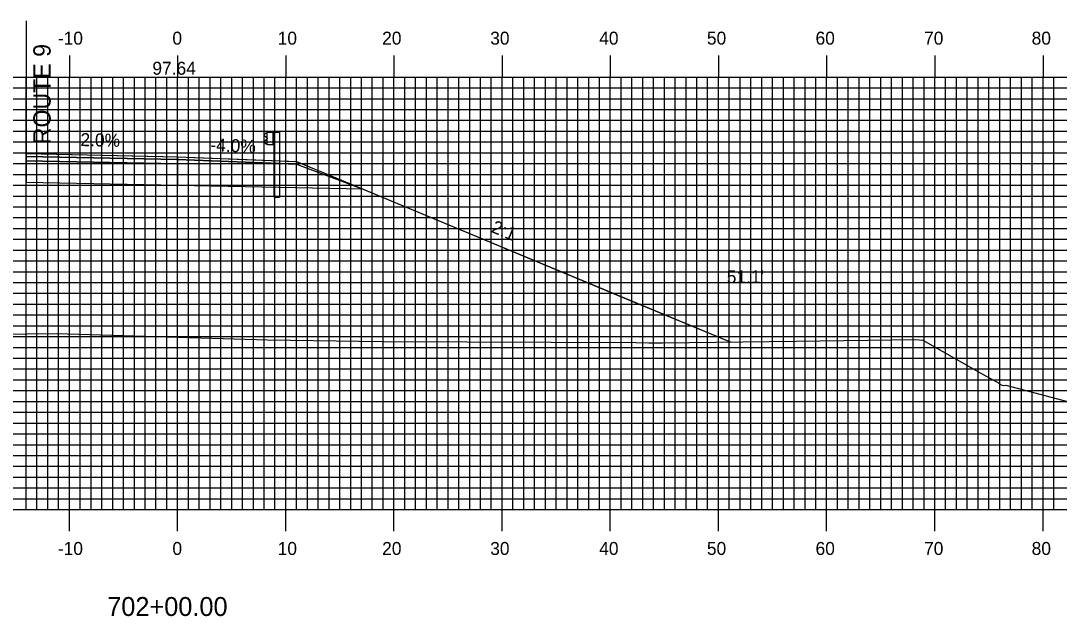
# Model space of a CAD drawing. Extents: x 852936 to 853279, y 364366 to 364586.
# Drawn here: x 853087.2 to 853183.2, y 364428.9 to 364484 of the extents above; entities that cross this region are included whole.
import ezdxf

# ---------------------------------------------------------------- set-up
doc = ezdxf.new("R2010")
doc.units = 0
for name, color, linetype in [('ANNOTATION', 7, 'Continuous'), ('D_Guardrail_Beam_Rt', 7, 'Continuous'), ('D_Roadway_Centerline', 7, 'Continuous'), ('D_Roadway_Centerline_Text', 7, 'Continuous'), ('D_Roadway_Edge_Shoulder', 7, 'Continuous'), ('D_Roadway_Edge_TW', 7, 'Continuous'), ('D_Roadway_Pavement', 7, 'Continuous'), ('D_Roadway_SlopeLines', 7, 'Continuous'), ('D_Roadway_SubGrade', 7, 'Continuous'), ('D_Text_Standard', 7, 'Continuous'), ('H_V ANNOTATION', 7, 'Continuous'), ('MAJOR', 7, 'Continuous'), ('MINOR', 7, 'Continuous'), ('S_Roadway_Centerline', 7, 'Continuous')]:
    doc.layers.add(name, color=color, linetype=linetype)

msp = doc.modelspace()

# ---------------------------------------------------------------- linework, layer by layer
at = {"layer": 'D_Guardrail_Beam_Rt'}
for p, q in [((853109.962, 364473.605), (853109.888, 364473.59)), ((853109.962, 364473.688), (853110.65, 364473.688)), ((853109.962, 364472.522), (853109.962, 364473.688)), ((853110.483, 364473.688), (853110.483, 364472.522)), ((853110.587, 364473.688), (853110.587, 364472.522)), ((853110.65, 364473.688), (853111.121, 364473.688)), ((853110.65, 364473.688), (853110.65, 364472.522)), ((853111.121, 364473.688), (853111.121, 364467.688)), ((853109.872, 364473.584), (853109.729, 364473.484)), ((853109.729, 364473.341), (853109.924, 364473.205)), ((853109.924, 364473.006), (853109.729, 364472.869)), ((853109.729, 364472.726), (853109.872, 364472.626)), ((853109.958, 364473.14), (853109.958, 364473.07)), ((853109.888, 364472.62), (853109.962, 364472.605)), ((853110.65, 364472.522), (853109.962, 364472.522)), ((853110.629, 364467.688), (853110.629, 364472.522)), ((853110.629, 364467.688), (853111.121, 364467.688))]:
    msp.add_line(p, q, dxfattribs=at)
for centre, major_axis, start_param, end_param in [((853109.779, 364473.412), (-0.0877, 0), 5.323254, 7.243116), ((853109.779, 364472.798), (-0.0877, 0), 5.323254, 7.243116), ((853109.896, 364473.55), (-0.0417, 0), 4.907132, 5.323254), ((853109.879, 364473.14), (0.0789, 0), 0, 0.959931), ((853109.879, 364473.07), (0.0789, 0), 5.323254, 6.283185), ((853109.896, 364472.66), (-0.0417, 0), 0.959931, 1.376053)]:
    msp.add_ellipse(centre, major_axis=major_axis, ratio=0.995501, start_param=start_param, end_param=end_param, dxfattribs=at)
at = {"layer": 'D_Roadway_Centerline'}
msp.add_lwpolyline([(853087.691, 364471.705), (853097.591, 364471.507), (853101.691, 364471.425), (853107.349, 364471.199), (853109.691, 364471.105), (853111.813, 364471.02), (853112.691, 364470.985), (853117.044, 364469.168), (853118.859, 364468.415), (853142.791, 364458.424), (853152.76, 364454.288)], dxfattribs=at)
at = {"layer": 'D_Roadway_Edge_Shoulder'}
for points in [[(853101.691, 364471.425), (853112.691, 364470.985), (853112.691, 364470.735), (853101.691, 364471.175)], [(853101.691, 364471.425), (853109.691, 364471.105), (853109.691, 364471.105), (853112.691, 364470.985), (853112.691, 364470.735), (853101.691, 364471.175)], [(853101.691, 364471.425), (853109.691, 364471.105), (853109.691, 364471.105), (853112.691, 364470.985), (853112.691, 364470.735), (853101.691, 364471.175)], [(853101.691, 364471.425), (853112.691, 364470.985), (853112.691, 364470.735), (853101.691, 364471.175)], [(853101.691, 364471.425), (853112.691, 364470.985), (853112.691, 364470.735), (853101.691, 364471.175)]]:
    msp.add_lwpolyline(points, close=True, dxfattribs=at)
at = {"layer": 'D_Roadway_Edge_TW'}
msp.add_lwpolyline([(853087.691, 364471.705), (853101.691, 364471.425), (853101.691, 364471.175), (853087.691, 364471.455)], close=True, dxfattribs=at)
msp.add_lwpolyline([(853087.691, 364471.705), (853101.691, 364471.425), (853101.691, 364471.175), (853087.691, 364471.455)], close=True, dxfattribs=at)
msp.add_lwpolyline([(853087.691, 364471.705), (853101.691, 364471.425), (853101.691, 364471.175), (853087.691, 364471.455)], close=True, dxfattribs=at)
msp.add_lwpolyline([(853087.691, 364471.705), (853101.691, 364471.425), (853101.691, 364471.175), (853087.691, 364471.455)], close=True, dxfattribs=at)
at = {"layer": 'D_Roadway_Pavement'}
msp.add_lwpolyline([(853087.691, 364471.455), (853101.691, 364471.175), (853101.691, 364470.758), (853087.691, 364471.038)], close=True, dxfattribs=at)
msp.add_lwpolyline([(853087.691, 364471.455), (853101.691, 364471.175), (853101.691, 364470.758), (853087.691, 364471.038)], close=True, dxfattribs=at)
msp.add_lwpolyline([(853087.691, 364471.455), (853101.691, 364471.175), (853101.691, 364470.758), (853087.691, 364471.038)], close=True, dxfattribs=at)
msp.add_lwpolyline([(853087.691, 364471.455), (853101.691, 364471.175), (853101.691, 364470.758), (853087.691, 364471.038)], close=True, dxfattribs=at)
msp.add_lwpolyline([(853101.691, 364471.175), (853101.691, 364470.758)], dxfattribs=at)
msp.add_lwpolyline([(853101.691, 364471.175), (853101.691, 364470.758)], dxfattribs=at)
msp.add_lwpolyline([(853101.691, 364471.175), (853101.691, 364470.758)], dxfattribs=at)
msp.add_lwpolyline([(853101.691, 364471.175), (853101.691, 364470.758)], dxfattribs=at)
msp.add_lwpolyline([(853101.691, 364471.175), (853101.691, 364470.758)], dxfattribs=at)
msp.add_lwpolyline([(853101.691, 364471.175), (853101.691, 364470.758)], dxfattribs=at)
msp.add_lwpolyline([(853101.691, 364471.175), (853101.691, 364470.758)], dxfattribs=at)
msp.add_lwpolyline([(853101.691, 364471.175), (853101.691, 364470.758)], dxfattribs=at)
msp.add_lwpolyline([(853101.691, 364471.175), (853101.691, 364470.758)], dxfattribs=at)
msp.add_lwpolyline([(853101.691, 364471.175), (853101.691, 364470.758)], dxfattribs=at)
msp.add_lwpolyline([(853101.691, 364471.175), (853101.691, 364470.758)], dxfattribs=at)
msp.add_lwpolyline([(853101.691, 364471.175), (853101.691, 364470.758)], dxfattribs=at)
msp.add_lwpolyline([(853101.691, 364471.175), (853101.691, 364470.758)], dxfattribs=at)
msp.add_lwpolyline([(853101.691, 364471.175), (853101.691, 364470.758)], dxfattribs=at)
at = {"layer": 'D_Roadway_SlopeLines'}
msp.add_lwpolyline([(853112.691, 364470.985), (853152.76, 364454.288)], dxfattribs=at)
msp.add_lwpolyline([(853112.691, 364470.985), (853152.76, 364454.288)], dxfattribs=at)
msp.add_lwpolyline([(853112.691, 364470.985), (853152.76, 364454.288)], dxfattribs=at)
msp.add_lwpolyline([(853112.691, 364470.985), (853152.76, 364454.288)], dxfattribs=at)
at = {"layer": 'D_Roadway_SubGrade'}
msp.add_line((853087.691, 364483.995), (853087.691, 364469.038), dxfattribs=at)
for points in [[(853087.691, 364471.038), (853101.691, 364470.758), (853101.691, 364468.758), (853087.691, 364469.038)], [(853087.691, 364471.038), (853101.691, 364470.758), (853101.691, 364468.758), (853087.691, 364469.038)], [(853087.691, 364471.038), (853101.691, 364470.758), (853101.691, 364468.758), (853087.691, 364469.038)], [(853087.691, 364471.038), (853101.691, 364470.758), (853101.691, 364468.758), (853087.691, 364469.038)], [(853101.691, 364470.758), (853101.691, 364471.175), (853112.691, 364470.735), (853112.691, 364470.985), (853118.859, 364468.415), (853101.691, 364468.758)], [(853101.691, 364470.758), (853101.691, 364471.175), (853112.691, 364470.735), (853112.691, 364470.985), (853118.859, 364468.415), (853101.691, 364468.758)], [(853101.691, 364470.758), (853101.691, 364471.175), (853112.691, 364470.735), (853112.691, 364470.985), (853118.859, 364468.415), (853101.691, 364468.758)], [(853101.691, 364470.758), (853101.691, 364471.175), (853112.691, 364470.735), (853118.859, 364468.415), (853101.691, 364468.758)], [(853101.691, 364470.758), (853101.691, 364471.175), (853112.691, 364470.735), (853112.691, 364470.985), (853118.859, 364468.415), (853101.691, 364468.758)]]:
    msp.add_lwpolyline(points, close=True, dxfattribs=at)
at = {"layer": 'MAJOR'}
for p, q in [((853091.691, 364480.791), (853091.691, 364478.787)), ((853101.691, 364480.791), (853101.691, 364478.787)), ((853111.691, 364480.791), (853111.691, 364478.787)), ((853121.691, 364480.791), (853121.691, 364478.787)), ((853131.691, 364480.791), (853131.691, 364478.787)), ((853141.691, 364480.791), (853141.691, 364478.787)), ((853151.691, 364480.791), (853151.691, 364478.787)), ((853161.691, 364480.791), (853161.691, 364478.787)), ((853171.691, 364480.791), (853171.691, 364478.787)), ((853181.691, 364480.791), (853181.691, 364478.787)), ((852961.691, 364478.787), (853241.691, 364478.787)), ((852961.691, 364478.787), (853241.691, 364478.787)), ((853091.691, 364438.787), (853091.691, 364478.787)), ((853101.691, 364438.787), (853101.691, 364478.787)), ((853111.691, 364438.787), (853111.691, 364478.787)), ((853121.691, 364438.787), (853121.691, 364478.787)), ((853131.691, 364438.787), (853131.691, 364478.787)), ((853141.691, 364438.787), (853141.691, 364478.787)), ((853151.691, 364438.787), (853151.691, 364478.787)), ((853161.691, 364438.787), (853161.691, 364478.787)), ((853171.691, 364438.787), (853171.691, 364478.787)), ((853181.691, 364438.787), (853181.691, 364478.787)), ((852961.691, 364473.787), (853241.691, 364473.787)), ((852961.691, 364468.787), (853241.691, 364468.787)), ((852961.691, 364463.787), (853241.691, 364463.787)), ((852961.691, 364458.787), (853241.691, 364458.787)), ((852961.691, 364453.787), (853241.691, 364453.787)), ((852961.691, 364448.787), (853241.691, 364448.787)), ((852961.691, 364443.787), (853241.691, 364443.787)), ((852961.691, 364438.787), (853241.691, 364438.787)), ((852961.691, 364438.787), (853241.691, 364438.787)), ((853091.691, 364436.783), (853091.691, 364438.787)), ((853101.691, 364436.783), (853101.691, 364438.787)), ((853111.691, 364436.783), (853111.691, 364438.787)), ((853121.691, 364436.783), (853121.691, 364438.787)), ((853131.691, 364436.783), (853131.691, 364438.787)), ((853141.691, 364436.783), (853141.691, 364438.787)), ((853151.691, 364436.783), (853151.691, 364438.787)), ((853161.691, 364436.783), (853161.691, 364438.787)), ((853171.691, 364436.783), (853171.691, 364438.787)), ((853181.691, 364436.783), (853181.691, 364438.787))]:
    msp.add_line(p, q, dxfattribs=at)
at = {"layer": 'MINOR'}
for p, q in [((853087.691, 364438.787), (853087.691, 364478.787)), ((853088.691, 364438.787), (853088.691, 364478.787)), ((853089.691, 364438.787), (853089.691, 364478.787)), ((853090.691, 364438.787), (853090.691, 364478.787)), ((853092.691, 364438.787), (853092.691, 364478.787)), ((853093.691, 364438.787), (853093.691, 364478.787)), ((853094.691, 364438.787), (853094.691, 364478.787)), ((853095.691, 364438.787), (853095.691, 364478.787)), ((853096.691, 364438.787), (853096.691, 364478.787)), ((853097.691, 364438.787), (853097.691, 364478.787)), ((853098.691, 364438.787), (853098.691, 364478.787)), ((853099.691, 364438.787), (853099.691, 364478.787)), ((853100.691, 364438.787), (853100.691, 364478.787)), ((853102.691, 364438.787), (853102.691, 364478.787)), ((853103.691, 364438.787), (853103.691, 364478.787)), ((853104.691, 364438.787), (853104.691, 364478.787)), ((853105.691, 364438.787), (853105.691, 364478.787)), ((853106.691, 364438.787), (853106.691, 364478.787)), ((853107.691, 364438.787), (853107.691, 364478.787)), ((853108.691, 364438.787), (853108.691, 364478.787)), ((853109.691, 364438.787), (853109.691, 364478.787)), ((853110.691, 364438.787), (853110.691, 364478.787)), ((853112.691, 364438.787), (853112.691, 364478.787)), ((853113.691, 364438.787), (853113.691, 364478.787)), ((853114.691, 364438.787), (853114.691, 364478.787)), ((853115.691, 364438.787), (853115.691, 364478.787)), ((853116.691, 364438.787), (853116.691, 364478.787)), ((853117.691, 364438.787), (853117.691, 364478.787)), ((853118.691, 364438.787), (853118.691, 364478.787)), ((853119.691, 364438.787), (853119.691, 364478.787)), ((853120.691, 364438.787), (853120.691, 364478.787)), ((853122.691, 364438.787), (853122.691, 364478.787)), ((853123.691, 364438.787), (853123.691, 364478.787)), ((853124.691, 364438.787), (853124.691, 364478.787)), ((853125.691, 364438.787), (853125.691, 364478.787)), ((853126.691, 364438.787), (853126.691, 364478.787)), ((853127.691, 364438.787), (853127.691, 364478.787)), ((853128.691, 364438.787), (853128.691, 364478.787)), ((853129.691, 364438.787), (853129.691, 364478.787)), ((853130.691, 364438.787), (853130.691, 364478.787)), ((853132.691, 364438.787), (853132.691, 364478.787)), ((853133.691, 364438.787), (853133.691, 364478.787)), ((853134.691, 364438.787), (853134.691, 364478.787)), ((853135.691, 364438.787), (853135.691, 364478.787)), ((853136.691, 364438.787), (853136.691, 364478.787)), ((853137.691, 364438.787), (853137.691, 364478.787)), ((853138.691, 364438.787), (853138.691, 364478.787)), ((853139.691, 364438.787), (853139.691, 364478.787)), ((853140.691, 364438.787), (853140.691, 364478.787)), ((853142.691, 364438.787), (853142.691, 364478.787)), ((853143.691, 364438.787), (853143.691, 364478.787)), ((853144.691, 364438.787), (853144.691, 364478.787)), ((853145.691, 364438.787), (853145.691, 364478.787)), ((853146.691, 364438.787), (853146.691, 364478.787)), ((853147.691, 364438.787), (853147.691, 364478.787)), ((853148.691, 364438.787), (853148.691, 364478.787)), ((853149.691, 364438.787), (853149.691, 364478.787)), ((853150.691, 364438.787), (853150.691, 364478.787)), ((853152.691, 364438.787), (853152.691, 364478.787)), ((853153.691, 364438.787), (853153.691, 364478.787)), ((853154.691, 364438.787), (853154.691, 364478.787)), ((853155.691, 364438.787), (853155.691, 364478.787)), ((853156.691, 364438.787), (853156.691, 364478.787)), ((853157.691, 364438.787), (853157.691, 364478.787)), ((853158.691, 364438.787), (853158.691, 364478.787)), ((853159.691, 364438.787), (853159.691, 364478.787)), ((853160.691, 364438.787), (853160.691, 364478.787)), ((853162.691, 364438.787), (853162.691, 364478.787)), ((853163.691, 364438.787), (853163.691, 364478.787)), ((853164.691, 364438.787), (853164.691, 364478.787)), ((853165.691, 364438.787), (853165.691, 364478.787)), ((853166.691, 364438.787), (853166.691, 364478.787)), ((853167.691, 364438.787), (853167.691, 364478.787)), ((853168.691, 364438.787), (853168.691, 364478.787)), ((853169.691, 364438.787), (853169.691, 364478.787)), ((853170.691, 364438.787), (853170.691, 364478.787)), ((853172.691, 364438.787), (853172.691, 364478.787)), ((853173.691, 364438.787), (853173.691, 364478.787)), ((853174.691, 364438.787), (853174.691, 364478.787)), ((853175.691, 364438.787), (853175.691, 364478.787)), ((853176.691, 364438.787), (853176.691, 364478.787)), ((853177.691, 364438.787), (853177.691, 364478.787)), ((853178.691, 364438.787), (853178.691, 364478.787)), ((853179.691, 364438.787), (853179.691, 364478.787)), ((853180.691, 364438.787), (853180.691, 364478.787)), ((853182.691, 364438.787), (853182.691, 364478.787)), ((852961.691, 364477.787), (853241.691, 364477.787)), ((852961.691, 364476.787), (853241.691, 364476.787)), ((852961.691, 364475.787), (853241.691, 364475.787)), ((852961.691, 364474.787), (853241.691, 364474.787)), ((852961.691, 364472.787), (853241.691, 364472.787)), ((852961.691, 364471.787), (853241.691, 364471.787)), ((852961.691, 364470.787), (853241.691, 364470.787)), ((852961.691, 364469.787), (853241.691, 364469.787)), ((852961.691, 364467.787), (853241.691, 364467.787)), ((852961.691, 364466.787), (853241.691, 364466.787)), ((852961.691, 364465.787), (853241.691, 364465.787)), ((852961.691, 364464.787), (853241.691, 364464.787)), ((852961.691, 364462.787), (853241.691, 364462.787)), ((852961.691, 364461.787), (853241.691, 364461.787)), ((852961.691, 364460.787), (853241.691, 364460.787)), ((852961.691, 364459.787), (853241.691, 364459.787)), ((852961.691, 364457.787), (853241.691, 364457.787)), ((852961.691, 364456.787), (853241.691, 364456.787)), ((852961.691, 364455.787), (853241.691, 364455.787)), ((852961.691, 364454.787), (853241.691, 364454.787)), ((852961.691, 364452.787), (853241.691, 364452.787)), ((852961.691, 364451.787), (853241.691, 364451.787)), ((852961.691, 364450.787), (853241.691, 364450.787)), ((852961.691, 364449.787), (853241.691, 364449.787)), ((852961.691, 364447.787), (853241.691, 364447.787)), ((852961.691, 364446.787), (853241.691, 364446.787)), ((852961.691, 364445.787), (853241.691, 364445.787)), ((852961.691, 364444.787), (853241.691, 364444.787)), ((852961.691, 364442.787), (853241.691, 364442.787)), ((852961.691, 364441.787), (853241.691, 364441.787)), ((852961.691, 364440.787), (853241.691, 364440.787)), ((852961.691, 364439.787), (853241.691, 364439.787))]:
    msp.add_line(p, q, dxfattribs=at)
at = {"layer": 'S_Roadway_Centerline'}
msp.add_lwpolyline([(853082.385, 364454.985), (853090.464, 364455.056), (853110.015, 364454.469), (853120.588, 364454.328), (853144.05, 364454.236), (853145.252, 364454.206), (853146.525, 364454.2), (853158.864, 364454.375), (853169.912, 364454.527), (853170.577, 364454.451), (853175.936, 364451.415), (853177.679, 364450.431), (853177.759, 364450.339), (853177.905, 364450.288), (853178.039, 364450.267), (853178.252, 364450.285), (853184.546, 364448.63)], dxfattribs=at)

# ---------------------------------------------------------------- texts
at = {"layer": 'ANNOTATION'}
for s, height, rotation, p in [('ROUTE 9', 1.6, 90, (853089.952, 364472.575)), ('2.0%', 1.2, 358.85424, (853092.698, 364472.405)), ('-4.0%', 1.2, 357.70939, (853104.706, 364471.935)), ('2:1', 1.2, 337.34076, (853130.605, 364464.479))]:
    msp.add_text(s, height=height, rotation=rotation, dxfattribs=at).set_placement(p)
at = {"layer": 'D_Roadway_Centerline_Text'}
msp.add_text('97.64', height=1.2, dxfattribs=at).set_placement((853099.358, 364479.003))
at = {"layer": 'D_Text_Standard'}
msp.add_text("51.1'", height=1.2, dxfattribs=at).set_placement((853152.456, 364459.719))
at = {"layer": 'H_V ANNOTATION'}
for s, height, p in [('-10', 1.2, (853090.621, 364481.787)), ('0', 1.2, (853101.21, 364481.787)), ('10', 1.2, (853110.942, 364481.787)), ('20', 1.2, (853120.599, 364481.787)), ('30', 1.2, (853130.589, 364481.787)), ('40', 1.2, (853140.664, 364481.787)), ('50', 1.2, (853150.621, 364481.787)), ('60', 1.2, (853160.664, 364481.787)), ('70', 1.2, (853170.696, 364481.787)), ('80', 1.2, (853180.642, 364481.787)), ('-10', 1.2, (853090.621, 364434.587)), ('0', 1.2, (853101.21, 364434.587)), ('10', 1.2, (853110.942, 364434.587)), ('20', 1.2, (853120.599, 364434.587)), ('30', 1.2, (853130.589, 364434.587)), ('40', 1.2, (853140.664, 364434.587)), ('50', 1.2, (853150.621, 364434.587)), ('60', 1.2, (853160.664, 364434.587)), ('70', 1.2, (853170.696, 364434.587)), ('80', 1.2, (853180.642, 364434.587)), ('702+00.00', 1.75, (853095.183, 364428.943))]:
    msp.add_text(s, height=height, dxfattribs=at).set_placement(p)

doc.saveas('drawing.dxf')
